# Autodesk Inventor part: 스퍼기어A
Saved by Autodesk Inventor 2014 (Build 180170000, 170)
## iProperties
Created: 2025-02
Part Number: 스퍼기어A
Material: 강철, 탄소
Document SubType Name: Modeling
Designer: dg
Density: 7.87 g/cm^3
Appearance: 반연마
Mass: 640.846 g
Surface Area: 260.761 cm^2
Volume: 81.4289 cm^3
Author: jhkim
Creation Date: 2025-01-06
Sending System: Autodesk Inventor 2025
Preprocessor: ST-DEVELOPER v20
Author: dg
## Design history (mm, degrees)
node "스퍼기어A1"
node "솔리드1"
node "기준1"
